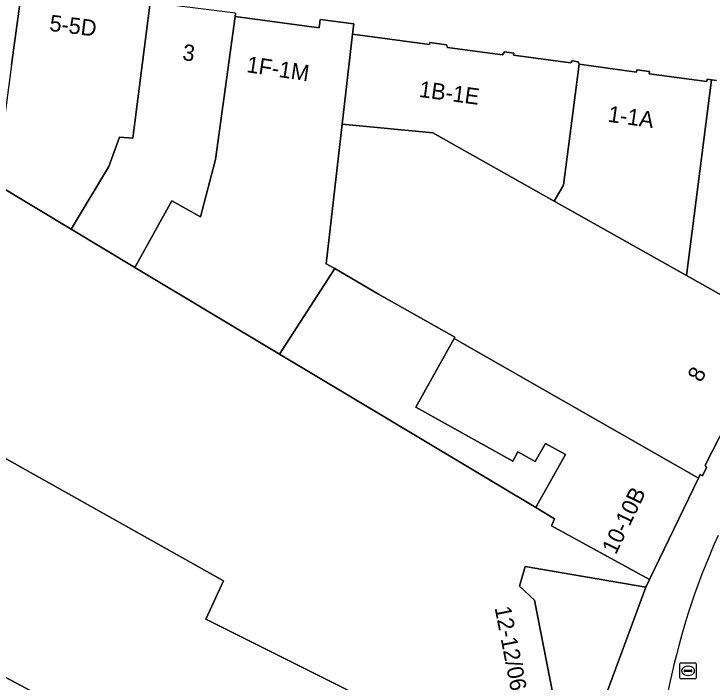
# Model space of a CAD drawing. Extents: x 160663 to 161506, y 382245 to 383291.
# Drawn here: x 161083.72 to 161126.71, y 383185.21 to 383226.33 of the extents above; entities that cross this region are included whole.
import ezdxf

# ---------------------------------------------------------------- set-up
doc = ezdxf.new("R2010")
doc.units = 0
for name, color, linetype in [('IMGEO_Erf', 7, 'Continuous'), ('IMGEO_Pand', 7, 'Continuous'), ('IMGEO_Pand_nummerreeks', 7, 'Continuous'), ('IMGEO_Pand_overbouw', 7, 'Continuous'), ('IMGEO_Rioolput', 7, 'Continuous'), ('IMGEO_Voetpad_open', 7, 'Continuous'), ('IMGEO_Woonerf_open', 7, 'Continuous')]:
    doc.layers.add(name, color=color, linetype=linetype)

msp = doc.modelspace()

# ---------------------------------------------------------------- linework, layer by layer
at = {"layer": 'IMGEO_Erf'}
for points in [[(161083.572, 383223.203), (161084.238, 383228.158), (161081.347, 383228.475)], [(161110.478, 383181.608), (161095.547, 383189.071), (161096.619, 383191.43), (161080.885, 383200.253)], [(161077.562, 383179.631), (161081.255, 383186.535), (161100.959, 383175.995)]]:
    msp.add_lwpolyline(points, dxfattribs=at)
msp.add_lwpolyline([(161110.829, 383206.349), (161110.878, 383206.437), (161106.162, 383209.071), (161103.479, 383210.652), (161100.073, 383205.392), (161115.85, 383195.94), (161116.004, 383196.217), (161117.676, 383199.211), (161116.446, 383199.897), (161115.822, 383198.78), (161114.758, 383199.374), (161114.436, 383198.798), (161108.472, 383202.129)], close=True, dxfattribs=at)
at = {"layer": 'IMGEO_Pand'}
for points in [[(161092.105, 383227.037), (161084.7, 383227.956), (161084.719, 383228.093), (161084.238, 383228.158), (161083.572, 383223.203), (161082.631, 383216.202), (161082.477, 383215.933), (161087.244, 383213.077), (161089.565, 383216.934), (161090.225, 383218.749), (161091.044, 383218.691)], [(161087.244, 383213.077), (161091.175, 383210.722), (161093.45, 383214.819), (161095.218, 383213.833), (161096.137, 383217.359), (161097.337, 383226.167), (161097.366, 383226.384), (161092.105, 383227.037), (161091.044, 383218.691), (161090.225, 383218.749), (161089.565, 383216.934)], [(161091.175, 383210.722), (161100.073, 383205.392), (161103.479, 383210.652), (161102.953, 383210.956), (161103.936, 383219.543), (161104.572, 383225.08), (161104.657, 383225.716), (161102.584, 383225.995), (161102.514, 383225.471), (161097.337, 383226.167), (161096.137, 383217.359), (161095.218, 383213.833), (161093.45, 383214.819)], [(161118.535, 383223.229), (161118.473, 383223.383), (161118.085, 383223.435), (161117.989, 383223.31), (161114.484, 383223.781), (161114.503, 383223.918), (161113.937, 383223.994), (161113.8, 383223.816), (161110.427, 383224.27), (161110.358, 383224.437), (161109.327, 383224.575), (161109.31, 383224.443), (161104.572, 383225.08), (161103.936, 383219.543), (161109.514, 383219.014), (161116.982, 383214.814), (161117.554, 383215.792)], [(161126.666, 383222.278), (161126.402, 383222.314), (161126.383, 383222.168), (161122.83, 383222.646), (161122.849, 383222.788), (161122.075, 383222.892), (161122.056, 383222.755), (161118.535, 383223.229), (161117.554, 383215.792), (161116.982, 383214.814), (161125.128, 383210.232)], [(161116.982, 383214.814), (161109.514, 383219.014), (161103.936, 383219.543), (161102.953, 383210.956), (161103.479, 383210.652), (161106.162, 383209.071), (161110.878, 383206.437), (161110.829, 383206.349), (161125.868, 383197.755), (161125.976, 383197.979), (161126.114, 383197.908), (161126.37, 383198.405), (161126.277, 383198.548), (161130.535, 383206.838), (161130.765, 383206.72), (161130.901, 383206.985), (161125.128, 383210.232)], [(161100.073, 383205.392), (161091.175, 383210.722), (161087.244, 383213.077), (161082.477, 383215.933), (161075.336, 383203.467), (161080.885, 383200.253), (161096.619, 383191.43), (161095.547, 383189.071), (161110.478, 383181.608), (161117.957, 383177.87), (161117.874, 383178.199), (161118.198, 383179.071), (161116.502, 383180.107), (161117.708, 383180.395), (161115.772, 383190.243), (161114.856, 383191.109), (161115.205, 383192.309), (161122.638, 383191.044), (161122.863, 383191.511), (161116.818, 383194.821), (161117.002, 383195.25), (161115.85, 383195.94)], [(161110.829, 383206.349), (161108.472, 383202.129), (161114.436, 383198.798), (161114.758, 383199.374), (161115.822, 383198.78), (161116.446, 383199.897), (161117.676, 383199.211), (161116.004, 383196.217), (161115.85, 383195.94), (161117.002, 383195.25), (161116.818, 383194.821), (161122.863, 383191.511), (161125.868, 383197.755)], [(161121.067, 383165.435), (161118.733, 383174.765), (161117.328, 383174.414), (161114.888, 383176.008), (161114.107, 383176.028), (161109.057, 383178.493), (161103.503, 383181.205), (161100.959, 383175.995), (161081.255, 383186.535), (161077.562, 383179.631), (161084.173, 383176.029), (161092.19, 383171.7), (161104.857, 383165.031), (161104.797, 383164.068), (161113.763, 383163.235), (161113.717, 383163.628)]]:
    msp.add_lwpolyline(points, close=True, dxfattribs=at)
msp.add_lwpolyline([(161126.974, 383222.237), (161126.666, 383222.278), (161125.128, 383210.232), (161130.901, 383206.985)], dxfattribs=at)
at = {"layer": 'IMGEO_Pand_overbouw'}
msp.add_lwpolyline([(161122.638, 383191.044), (161115.205, 383192.309), (161114.856, 383191.109), (161115.772, 383190.243), (161117.708, 383180.395), (161116.502, 383180.107), (161118.198, 383179.071)], close=True, dxfattribs=at)
at = {"layer": 'IMGEO_Rioolput'}
for p, q in [((161124.73, 383185.47), (161124.73, 383186.322)), ((161124.805, 383186.396), (161125.657, 383186.396)), ((161125.218, 383186.176), (161125.243, 383186.176)), ((161125.731, 383186.322), (161125.731, 383185.47)), ((161124.989, 383185.89), (161124.989, 383185.902)), ((161125.427, 383185.853), (161125.029, 383185.853)), ((161125.032, 383185.939), (161125.43, 383185.939)), ((161125.241, 383185.616), (161125.216, 383185.616)), ((161125.473, 383185.902), (161125.473, 383185.89)), ((161125.657, 383185.396), (161124.805, 383185.396))]:
    msp.add_line(p, q, dxfattribs=at)
for points in [[(161124.73, 383185.47), (161124.73, 383186.322)], [(161124.805, 383186.396), (161125.657, 383186.396)], [(161125.731, 383186.322), (161125.731, 383185.47)], [(161125.657, 383185.396), (161124.805, 383185.396)]]:
    msp.add_lwpolyline(points, dxfattribs=at)
for centre, radius, start, end in [((161124.807, 383186.32), 0.0765, 91.552, 178.448), ((161124.807, 383186.32), 0.0765, 91.552, 178.448), ((161125.655, 383186.32), 0.0765, 1.552, 88.448), ((161125.655, 383186.32), 0.0765, 1.552, 88.448), ((161125.029, 383185.899), 0.0403, 85.8775, 175.7526), ((161125.026, 383185.889), 0.0366, 178.938, 274.7102), ((161125.43, 383185.896), 0.043, 264.8664, 352.4533), ((161125.434, 383185.901), 0.0386, 1.7309, 96.639), ((161124.807, 383185.472), 0.0765, 181.552, 268.448), ((161124.807, 383185.472), 0.0765, 181.552, 268.448), ((161125.655, 383185.472), 0.0765, 271.552, 358.448), ((161125.655, 383185.472), 0.0765, 271.552, 358.448)]:
    msp.add_arc(centre, radius, start, end, dxfattribs=at)
for centre, major_axis, ratio, start_param, end_param in [((161125.217, 383185.896), (-0.387, 0.002), 0.722429, 4.712389, 7.853982), ((161125.242, 383185.896), (-0.39, 0.002), 0.717154, 1.570796, 4.712389)]:
    msp.add_ellipse(centre, major_axis=major_axis, ratio=ratio, start_param=start_param, end_param=end_param, dxfattribs=at)
at = {"layer": 'IMGEO_Voetpad_open'}
msp.add_lwpolyline([(161130.535, 383206.838), (161126.277, 383198.548), (161126.37, 383198.405), (161126.114, 383197.908), (161125.976, 383197.979), (161125.868, 383197.755), (161122.863, 383191.511), (161122.638, 383191.044), (161118.198, 383179.071)], dxfattribs=at)
msp.add_lwpolyline([(161122.638, 383191.044), (161115.205, 383192.309), (161114.856, 383191.109), (161115.772, 383190.243), (161117.708, 383180.395), (161116.502, 383180.107), (161118.198, 383179.071)], close=True, dxfattribs=at)
msp.add_arc((161167.542, 383175.962), 44.397, 155.6958, 169.1083, dxfattribs=at)
at = {"layer": 'IMGEO_Woonerf_open'}
msp.add_lwpolyline([(161097.366, 383226.384), (161097.337, 383226.167), (161102.514, 383225.471), (161102.584, 383225.995), (161104.657, 383225.716), (161104.572, 383225.08), (161109.31, 383224.443), (161109.327, 383224.575), (161110.358, 383224.437), (161110.427, 383224.27), (161113.8, 383223.816), (161113.937, 383223.994), (161114.503, 383223.918), (161114.484, 383223.781), (161117.989, 383223.31), (161118.085, 383223.435), (161118.473, 383223.383), (161118.535, 383223.229), (161122.056, 383222.755), (161122.075, 383222.892), (161122.849, 383222.788), (161122.83, 383222.646), (161126.383, 383222.168), (161126.402, 383222.314), (161126.666, 383222.278), (161126.974, 383222.237)], dxfattribs=at)
msp.add_arc((161167.542, 383175.962), 44.397, 155.6958, 169.1083, dxfattribs=at)

# ---------------------------------------------------------------- texts
at = {"layer": 'IMGEO_Pand_nummerreeks'}
for s, rotation, p in [('5-5D', 352.924, (161085.868, 383225.292)), ('3', 352.9251, (161094.058, 383223.49)), ('1F-1M', 351.4554, (161098.003, 383222.751)), ('1B-1E', 352.3567, (161108.626, 383221.226)), ('1-1A', 351.8296, (161120.256, 383219.701)), ('8', 62.8136, (161126.04, 383203.603)), ('10-10B', 64.2973, (161120.783, 383193.001)), ('12-12/06', 281.1209, (161113.316, 383189.776))]:
    msp.add_text(s, height=1, rotation=rotation, dxfattribs=at).set_placement(p)

doc.saveas('drawing.dxf')
